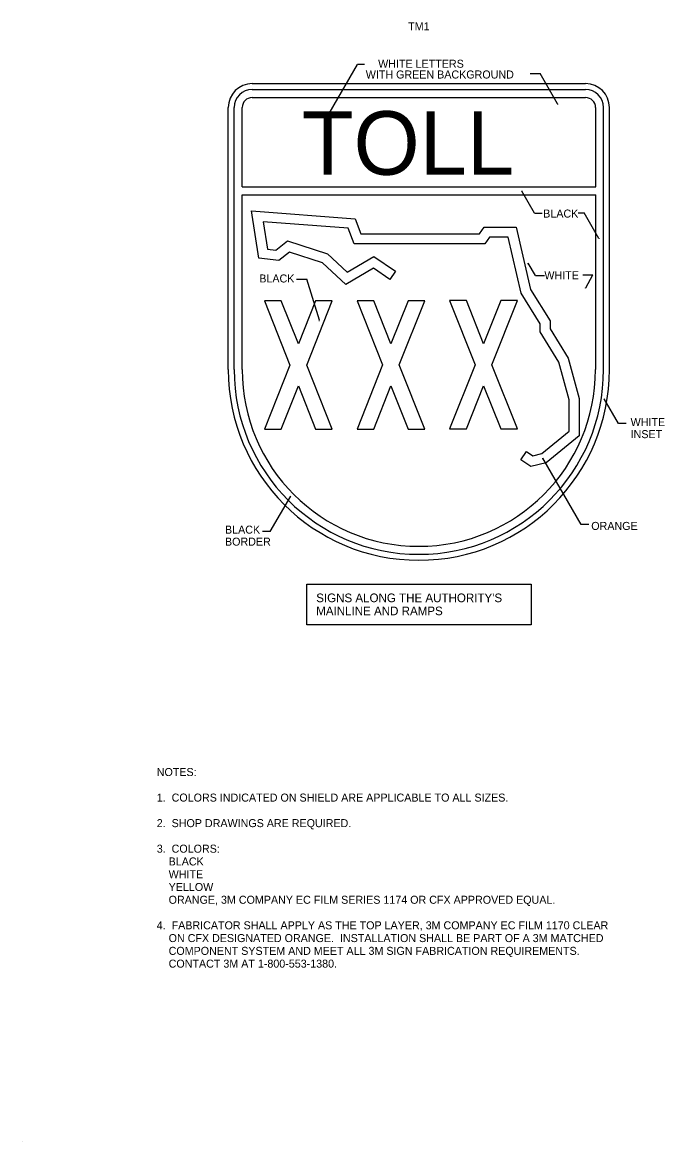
# Model space of a CAD drawing. Extents: x 52204 to 54080, y 10312 to 11487.
# Drawn here: x 52204 to 52878, y 10312 to 11487 of the extents above; entities that cross this region are included whole.
import ezdxf

# ---------------------------------------------------------------- set-up
doc = ezdxf.new("R2010")
doc.units = 0
for name, color, linetype in [('AdhocPoint_dp', 7, 'Continuous'), ('Default', 7, 'Continuous'), ('GSDims', 7, 'Continuous'), ('SignPanel', 7, 'Continuous'), ('TextAlert', 7, 'Continuous'), ('TextNotes', 7, 'Continuous')]:
    doc.layers.add(name, color=color, linetype=linetype)

msp = doc.modelspace()

# ---------------------------------------------------------------- linework, layer by layer
at = {"layer": 'AdhocPoint_dp'}
msp.add_line((52204.2, 10312.4), (52204.2, 10312.4), dxfattribs=at)
at = {"layer": 'GSDims'}
for p, q in [((52522.3, 11384.3), (52555.9, 11442.5)), ((52563.1, 11442.5), (52555.9, 11442.5)), ((52737, 11432.9), (52747.5, 11432.9)), ((52765.8, 11401.2), (52747.5, 11432.9)), ((52741.5, 11286.4), (52728.1, 11309.6)), ((52741.5, 11286.4), (52749.7, 11286.4)), ((52787.3, 11286.7), (52793.6, 11286.7)), ((52809.1, 11259.9), (52793.6, 11286.7)), ((52742.5, 11220.9), (52734.9, 11234.1)), ((52492, 11217.3), (52502.5, 11217.3)), ((52515.8, 11174.1), (52502.5, 11217.3)), ((52742.5, 11220.9), (52752, 11220.9)), ((52792.3, 11221.7), (52802.7, 11221.7)), ((52795.3, 11208), (52802.7, 11221.7)), ((52829.8, 11065.8), (52814.8, 11091.7)), ((52837.8, 11065.8), (52829.8, 11065.8)), ((52790.4, 10959.8), (52750.3, 11029.3)), ((52464.2, 10952.3), (52485.8, 10989.6)), ((52798.5, 10959.8), (52790.4, 10959.8)), ((52464.2, 10952.3), (52456.2, 10952.3))]:
    msp.add_line(p, q, dxfattribs=at)
at = {"layer": 'SignPanel'}
for p, q in [((52445.3, 11422.4), (52795.2, 11422.4)), ((52445.3, 11416.1), (52795.2, 11416.1)), ((52445.3, 11407.8), (52795.2, 11407.8)), ((52420.2, 11122.3), (52420.3, 11397.4)), ((52426.4, 11122.3), (52426.5, 11397.4)), ((52434.8, 11314), (52434.8, 11397.4)), ((52805.8, 11314), (52805.8, 11397.4)), ((52814.1, 11122.3), (52814.1, 11397.4)), ((52820.3, 11122.3), (52820.3, 11397.4)), ((52434.8, 11314), (52487, 11314)), ((52487, 11314), (52805.8, 11314)), ((52434.7, 11122.3), (52434.8, 11305.7)), ((52434.8, 11305.7), (52805.8, 11305.7)), ((52805.8, 11122.3), (52805.8, 11305.7)), ((52444.6, 11288.9), (52553.3, 11280.5)), ((52452.4, 11239.2), (52444.6, 11288.9)), ((52545.9, 11270.6), (52457, 11277.4)), ((52457, 11277.4), (52461.5, 11248.6)), ((52553.3, 11280.5), (52559.4, 11264.9)), ((52552.2, 11254.4), (52545.9, 11270.6)), ((52559.4, 11264.9), (52684, 11264.9)), ((52684, 11264.9), (52688.7, 11271.8)), ((52688.7, 11271.8), (52722.2, 11271.8)), ((52694.2, 11261.4), (52689.6, 11254.4)), ((52713.9, 11261.4), (52694.2, 11261.4)), ((52727.6, 11202.5), (52713.9, 11261.4)), ((52722.2, 11271.8), (52737.4, 11206.5)), ((52470.1, 11247.6), (52482.5, 11257.3)), ((52482.5, 11257.3), (52524.4, 11243.7)), ((52689.6, 11254.4), (52552.2, 11254.4)), ((52473.2, 11236.6), (52452.4, 11239.2)), ((52461.5, 11248.6), (52470.1, 11247.6)), ((52484.6, 11245.6), (52473.2, 11236.6)), ((52519, 11234.4), (52484.6, 11245.6)), ((52524.4, 11243.7), (52545, 11224.6)), ((52545, 11224.6), (52572.9, 11241)), ((52572.9, 11241), (52595.6, 11225.6)), ((52543.6, 11211.6), (52519, 11234.4)), ((52572.5, 11228.6), (52543.6, 11211.6)), ((52589.7, 11217), (52572.5, 11228.6)), ((52595.6, 11225.6), (52589.7, 11217)), ((52747.6, 11170.3), (52727.6, 11202.5)), ((52737.4, 11206.5), (52758.1, 11173.3)), ((52475.8, 11194.5), (52458.3, 11194.5)), ((52458.3, 11194.5), (52485, 11127.1)), ((52493.8, 11149.2), (52475.8, 11194.5)), ((52511.8, 11194.5), (52493.8, 11149.2)), ((52502.6, 11127.1), (52529.3, 11194.5)), ((52529.3, 11194.5), (52511.8, 11194.5)), ((52572.9, 11194.6), (52555.4, 11194.6)), ((52555.4, 11194.6), (52582.2, 11127.3)), ((52590.9, 11149.3), (52572.9, 11194.6)), ((52608.9, 11194.6), (52590.9, 11149.3)), ((52599.7, 11127.3), (52626.5, 11194.6)), ((52626.5, 11194.6), (52608.9, 11194.6)), ((52670.1, 11194.7), (52652.5, 11194.7)), ((52652.5, 11194.7), (52679.3, 11127.4)), ((52688.1, 11149.5), (52670.1, 11194.7)), ((52706.1, 11194.7), (52688.1, 11149.5)), ((52696.8, 11127.4), (52723.6, 11194.7)), ((52723.6, 11194.7), (52706.1, 11194.7)), ((52747.6, 11162), (52747.6, 11170.3)), ((52758.1, 11173.3), (52758.1, 11164.9)), ((52767, 11130), (52747.6, 11162)), ((52758.1, 11164.9), (52776.8, 11134.2)), ((52776.8, 11134.2), (52788.3, 11092)), ((52485, 11127.1), (52458.3, 11059.8)), ((52529.3, 11059.8), (52502.6, 11127.1)), ((52582.2, 11127.3), (52555.4, 11059.9)), ((52626.5, 11059.9), (52599.7, 11127.3)), ((52679.3, 11127.4), (52652.5, 11060)), ((52723.6, 11060), (52696.8, 11127.4)), ((52777.8, 11090.6), (52767, 11130)), ((52475.8, 11059.8), (52493.8, 11105.1)), ((52493.8, 11105.1), (52511.8, 11059.8)), ((52572.9, 11059.9), (52590.9, 11105.2)), ((52590.9, 11105.2), (52608.9, 11059.9)), ((52670.1, 11060), (52688.1, 11105.3)), ((52688.1, 11105.3), (52706.1, 11060)), ((52777.8, 11057.7), (52777.8, 11090.6)), ((52788.3, 11092), (52788.3, 11052.7)), ((52458.3, 11059.8), (52475.8, 11059.8)), ((52511.8, 11059.8), (52529.3, 11059.8)), ((52555.4, 11059.9), (52572.9, 11059.9)), ((52608.9, 11059.9), (52626.5, 11059.9)), ((52652.5, 11060), (52670.1, 11060)), ((52706.1, 11060), (52723.6, 11060)), ((52749.2, 11034.2), (52777.8, 11057.7)), ((52788.3, 11052.7), (52753.9, 11024.6)), ((52727.3, 11027.8), (52733.3, 11036.4)), ((52737.6, 11020.7), (52727.3, 11027.8)), ((52733.3, 11036.4), (52739.8, 11031.9)), ((52739.8, 11031.9), (52749.2, 11034.2)), ((52753.9, 11024.6), (52737.6, 11020.7))]:
    msp.add_line(p, q, dxfattribs=at)
for centre, radius, start, end in [((52445.3, 11397.3), 25, 90, 179.9792), ((52445.3, 11397.3), 18.8, 90, 179.9792), ((52795.2, 11397.3), 25, 0, 90), ((52795.2, 11397.3), 18.8, 0, 90), ((52445.3, 11397.3), 10.4, 90, 179.9792), ((52795.2, 11397.3), 10.4, 0, 90), ((52620.2, 11122.3), 200, 180, 0), ((52620.2, 11122.3), 193.8, 180, 0), ((52620.2, 11122.3), 185.4, 180, 0)]:
    msp.add_arc(centre, radius, start, end, dxfattribs=at)
at = {"layer": 'TextAlert'}
msp.add_lwpolyline([(52502.5, 10897.3), (52738, 10897.3), (52738, 10854.6), (52502.5, 10854.6)], close=True, dxfattribs=at)

# ---------------------------------------------------------------- texts
at = {"layer": 'Default'}
msp.add_text('TM1', height=8.4, dxfattribs=at).set_placement((52609, 11478.2))
at = {"layer": 'GSDims'}
for s, p in [('WHITE LETTERS', (52577.5, 11439)), ('WITH GREEN BACKGROUND', (52564.5, 11427.7)), ('.', (52520.8, 11383.5)), ('BLACK', (52750.7, 11281.8)), ('.', (52733.1, 11232.9)), ('WHITE', (52751.9, 11217.1)), ('BLACK', (52452.8, 11213.7)), ('.', (52514, 11173)), ('.', (52813, 11090.5)), ('WHITE', (52842.4, 11063)), ('INSET', (52842.4, 11050.4)), ('.', (52748.5, 11028.1)), ('.', (52483.9, 10988.3)), ('BLACK', (52416.8, 10950.2)), ('ORANGE', (52801.1, 10954.1)), ('BORDER', (52416.8, 10937.6))]:
    msp.add_text(s, height=8.4, dxfattribs=at).set_placement(p)
for rotation, p in [(90, (52766.6, 11399.3)), (90, (52729.1, 11308)), (301.5608, (52793.5, 11208.9))]:
    msp.add_text('.', height=8.4, rotation=rotation, dxfattribs=at).set_placement(p)
at = {"layer": 'SignPanel'}
msp.add_text('TOLL', height=66.65, dxfattribs=at).set_placement((52497.3, 11326.7))
msp.add_text('.', height=7.2, rotation=90, dxfattribs=at).set_placement((52810, 11258.4))
at = {"layer": 'TextAlert'}
for s, p in [("SIGNS ALONG THE AUTHORITY'S", (52512.5, 10878.3)), ('MAINLINE AND RAMPS', (52512.5, 10864.6))]:
    msp.add_text(s, height=9.072, dxfattribs=at).set_placement(p)
at = {"layer": 'TextNotes'}
for s, p in [('NOTES:', (52345.2, 10695.9)), ('1.  COLORS INDICATED ON SHIELD ARE APPLICABLE TO ALL SIZES.', (52345.2, 10669.1)), ('2.  SHOP DRAWINGS ARE REQUIRED.', (52345.2, 10642.3)), ('3.  COLORS:', (52345.2, 10615.5)), ('    BLACK', (52345.2, 10602.1)), ('    WHITE', (52345.2, 10588.7)), ('    YELLOW', (52345.2, 10575.3)), ('    ORANGE, 3M COMPANY EC FILM SERIES 1174 OR CFX APPROVED EQUAL.', (52345.2, 10561.9)), ('4.  FABRICATOR SHALL APPLY AS THE TOP LAYER, 3M COMPANY EC FILM 1170 CLEAR', (52345.2, 10535.1)), ('    ON CFX DESIGNATED ORANGE.  INSTALLATION SHALL BE PART OF A 3M MATCHED', (52345.2, 10521.7)), ('    COMPONENT SYSTEM AND MEET ALL 3M SIGN FABRICATION REQUIREMENTS.', (52345.2, 10508.3)), ('    CONTACT 3M AT 1-800-553-1380.', (52345.2, 10494.9))]:
    msp.add_text(s, height=8.4, dxfattribs=at).set_placement(p)

doc.saveas('drawing.dxf')
